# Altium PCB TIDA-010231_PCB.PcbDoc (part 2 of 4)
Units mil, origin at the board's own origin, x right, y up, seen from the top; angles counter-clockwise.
Board outline 3937.01 x 3740.16 mil, 4 copper layers (Top Layer, Signal Layer 1, Signal Layer 2, Bottom Layer), stack 65.355 mil thick; 295 components, 163 nets, 818 pads, 213 vias.
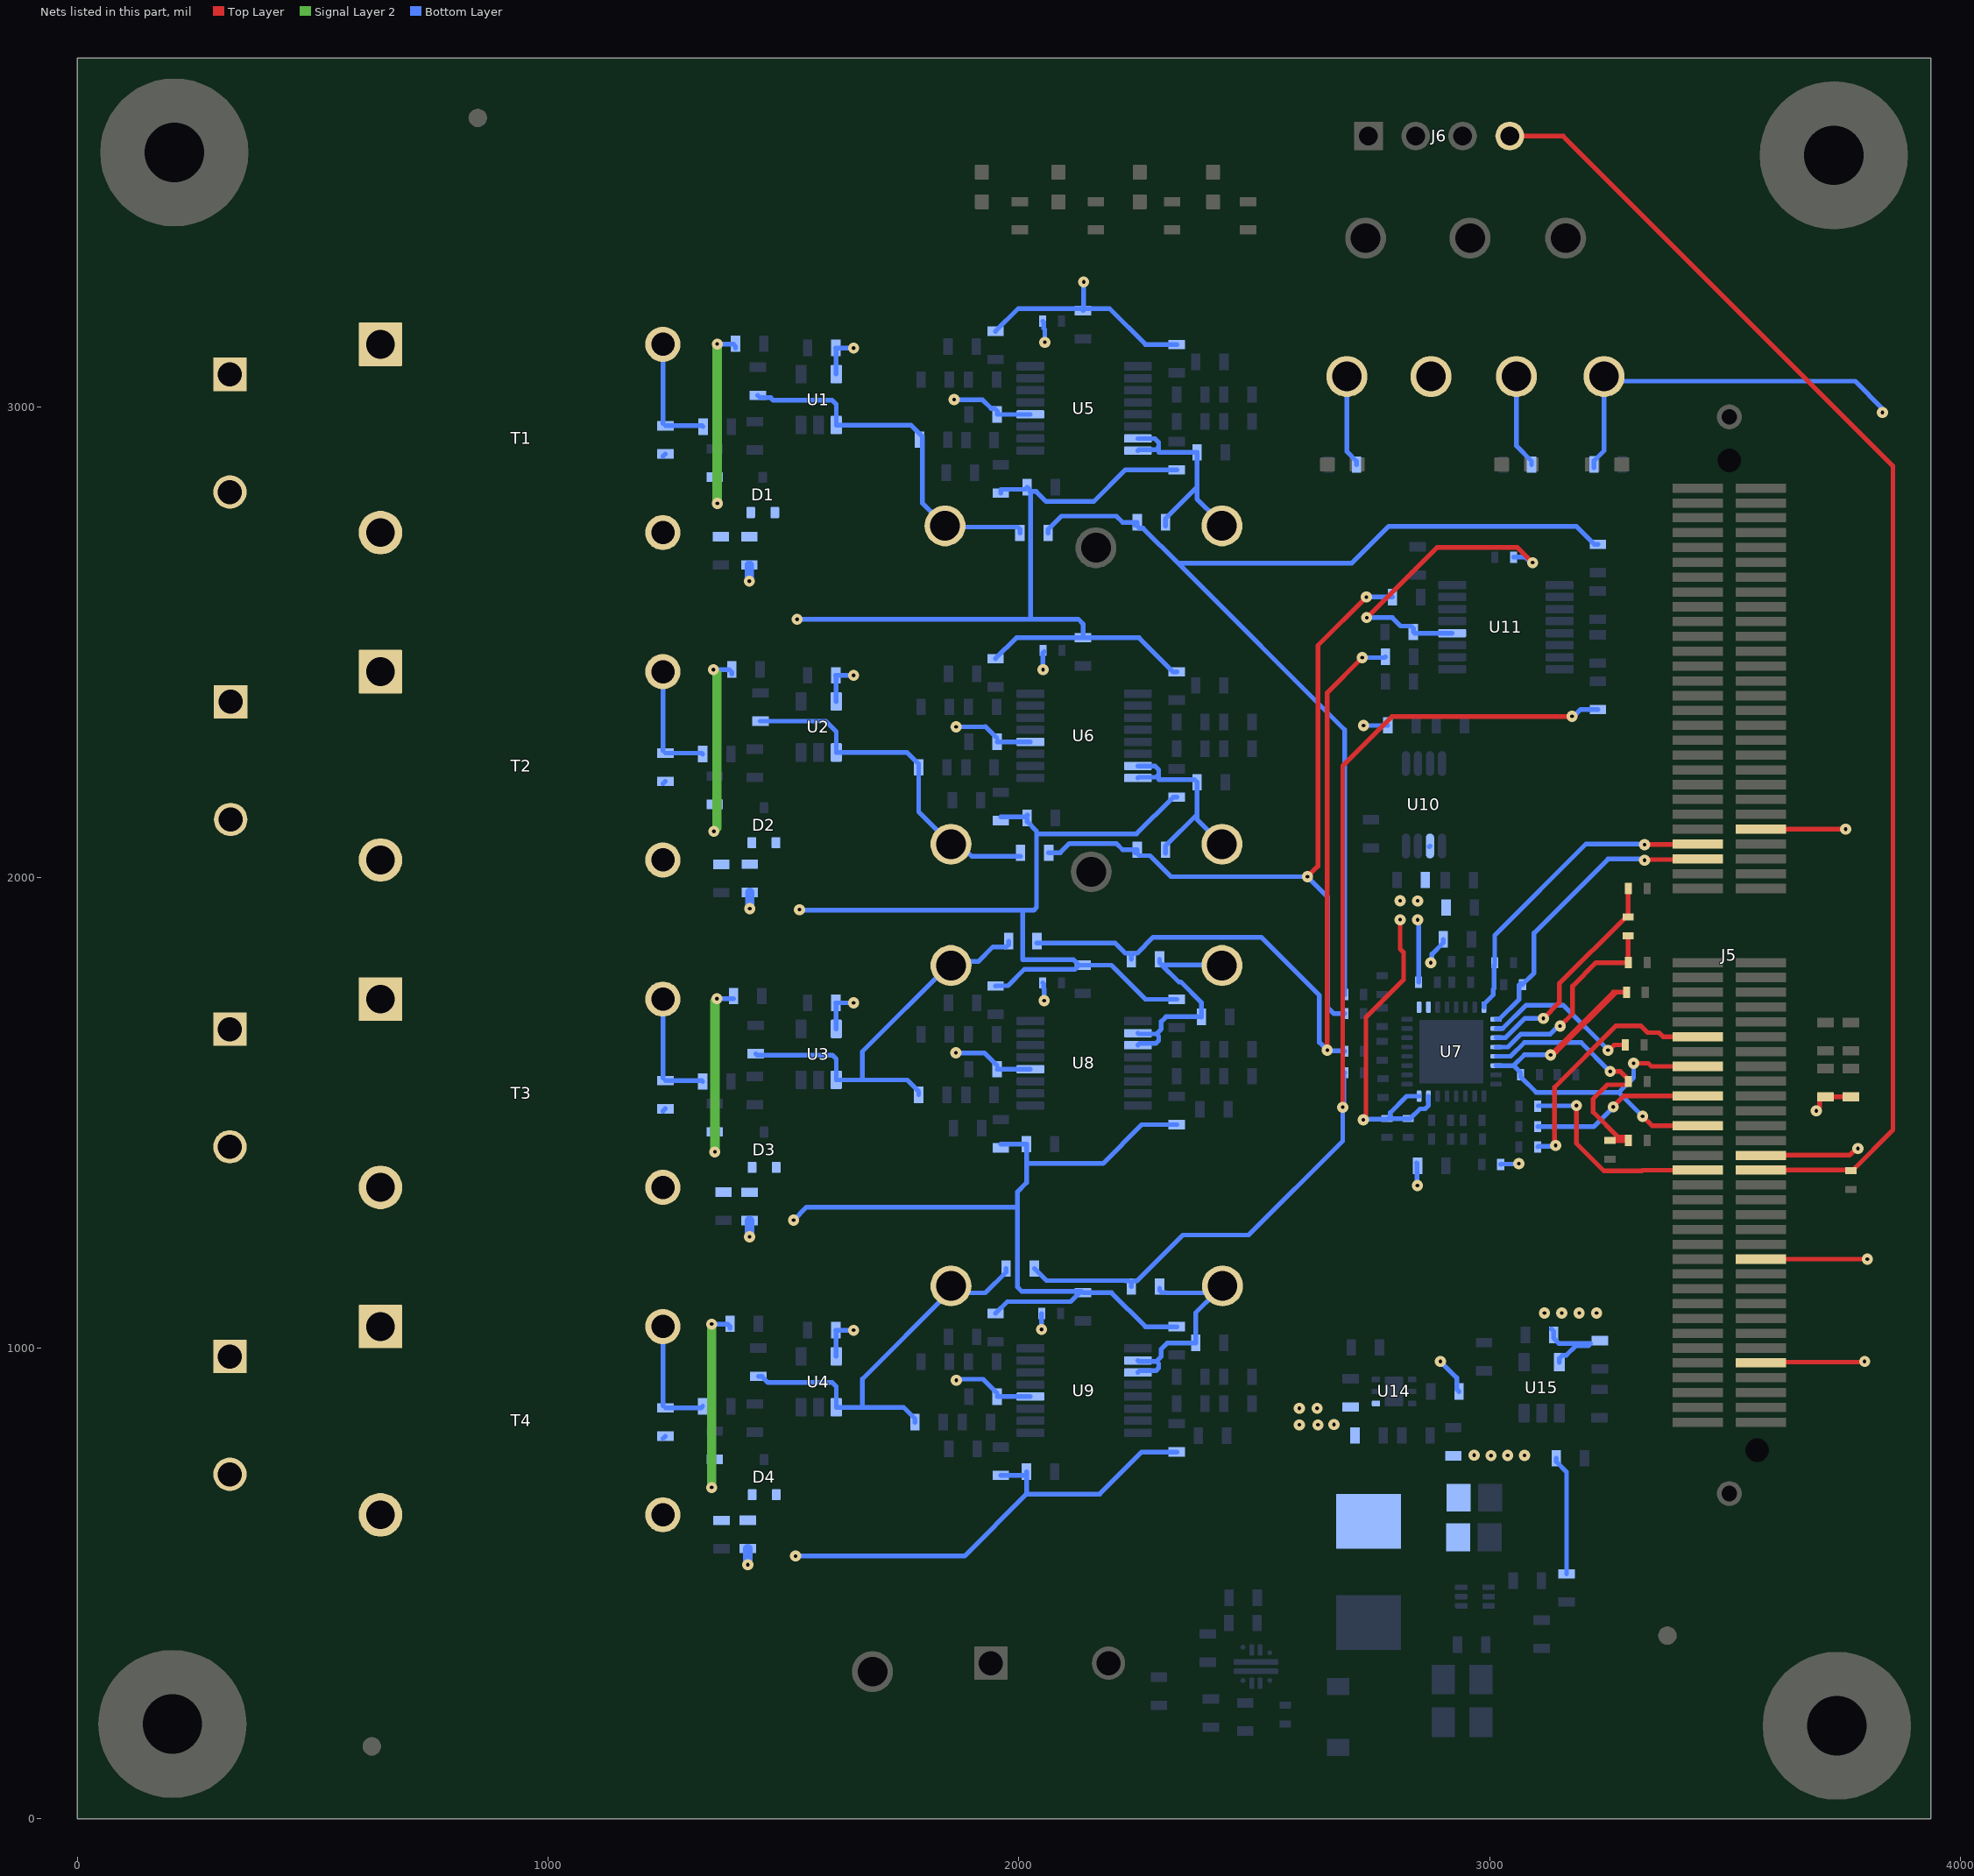
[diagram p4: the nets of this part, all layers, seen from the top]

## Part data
C1 C3 C5 C7: library part CMP-0006898-4, "CAP, CERM, 2200 pF, 50 V, +/- 10%, X7R, 0603", Cap_Case=0603, Manufacturer=Kemet, Supplier Part Number 1=399-1085-1-ND, TempCo=X7R, Tolerance_%=10%, Value1=Unknown, Value2=50V, ValueDisplayed=2200pF
C2 C4 C6 C8 C9 C10 C19 C20 C38 C39 C50 C51 C67 C68 C69 C70 C71 C87 C88 C89 C90: library part CMP-0079602-1, "CAP, CERM, 0.1 µF, 50 V,+/- 10%, X7R, AEC-Q200 Grade 1, 0603", Cap_Case=0603, Manufacturer=Kemet, Supplier Part Number 1=399-6856-1-ND, TempCo=X7R, Tolerance_%=10%, Value2=50V, ValueDisplayed=0.1µF
C11 C12 C25 C26 C40 C41 C54 C55: library part CMP-0006751-4, "CAP, CERM, 100 pF, 25 V, +/- 10%, X7R, 0603", Cap_Case=0603, Manufacturer=AVX, Supplier Part Number 1=55J3899, TempCo=X7R, Tolerance_%=10%, Value1=Unknown, Value2=25V, ValueDisplayed=100pF
C13 C27 C42 C56: library part CMP-0007162-4, "CAP, CERM, 1300 pF, 25 V, +/- 5%, C0G/NP0, 0603", Cap_Case=0603, Manufacturer=MuRata, Supplier Part Number 1=GRM1885C1E132JA01D-ND, TempCo=C0G/NP0, Tolerance_%=5%, Value1=Unknown, Value2=25V, ValueDisplayed=1300pF
C14 C28 C43 C57: library part CMP-0007432-5, "CAP, CERM, 1000 pF, 50 V, +/- 10%, X7R, 0603", Cap_Case=0603, Manufacturer=MuRata, Supplier Part Number 1=490-1494-1-ND, TempCo=X7R, Tolerance_%=10%, Value1=Unknown, Value2=50V, ValueDisplayed=1000pF
C15 C29 C44 C58: library part CMP-0007216-4, "CAP, CERM, 3900 pF, 50 V, +/- 5%, C0G/NP0, 0603", Cap_Case=0603, Manufacturer=MuRata, Supplier Part Number 1=GRM1885C1H392JA01D-ND, TempCo=C0G/NP0, Tolerance_%=5%, Value1=Unknown, Value2=50V, ValueDisplayed=3900pF
C16 C30 C45 C59: library part CMP-0006983-4, "CAP, CERM, 2200 pF, 50 V, +/- 10%, X7R, 0603", Cap_Case=0603, Manufacturer=Kemet, Supplier Part Number 1=399-5341-1-ND, TempCo=X7R, Tolerance_%=10%, Value1=Unknown, Value2=50V, ValueDisplayed=2200pF
C17 C33 C47 C61: library part CMP-0007185-4, "CAP, CERM, 150 pF, 50 V, +/- 5%, C0G/NP0, 0603", Cap_Case=0603, Manufacturer=MuRata, Supplier Part Number 1=490-1431-1-ND, TempCo=C0G/NP0, Tolerance_%=5%, Value1=Unknown, Value2=50V, ValueDisplayed=150pF
C18 C34 C48 C62: library part CMP-0006784-4, "CAP, CERM, 330 pF, 50 V, +/- 5%, C0G/NP0, 0603", Cap_Case=0603, Manufacturer=AVX, Supplier Part Number 1=478-1181-1-ND, TempCo=C0G/NP0, Tolerance_%=5%, Value1="0.071 ohm", Value2=50V, ValueDisplayed=330pF
C21 C24 C31: library part CMP-0006638-2, "CAP, CERM, 1000 pF, 16 V, +/- 10%, X7R, 0402", Cap_Case=0402, Manufacturer=MuRata, Supplier Part Number 1=GRM155R71C102KA01D-ND, TempCo=X7R, Tolerance_%=10%, Value1=Unknown, Value2=16V, ValueDisplayed=1000pF
C22 C23 C32: library part CMP-0006624-2, "CAP, CERM, 1 uF, 6.3 V, +/- 20%, X7R, 0402", Cap_Case=0402, Manufacturer=MuRata, Supplier Part Number 1=490-9665-1-ND, TempCo=X7R, Tolerance_%=20%, Value1=Unknown, Value2=6.3V, ValueDisplayed=1uF
C35: library part CMP-0006233-2, "CAP, CERM, 100 pF, 25 V, +/- 5%, C0G/NP0, 0402", Cap_Case=0402, Manufacturer=Kemet, Supplier Part Number 1=399-1022-1-ND, TempCo=C0G/NP0, Tolerance_%=5%, Value1=Unknown, Value2=25V, ValueDisplayed=100pF
C36 C37 C49 C52: library part CMP-0079620-1, "CAP, CERM, 1500 pF, 50 V,+/- 5%, X7R, 0402", Cap_Case=0402, Manufacturer=MuRata, Supplier Part Number 1=490-10779-1-ND, TempCo=X7R, Tolerance_%=5%, Value2=50V, ValueDisplayed=1500pF
C46 C60: library part CMP-0006564-2, "CAP, CERM, 10 uF, 10 V, +/- 20%, X5R, 0402", Cap_Case=0402, Manufacturer=MuRata, TempCo=X5R, Tolerance_%=20%, Value1=Unknown, Value2=10V, ValueDisplayed=10uF
C53: library part CMP-0006545-2, "CAP, CERM, 22 uF, 6.3 V, +/- 20%, X5R, 0402", Cap_Case=0402, Manufacturer=MuRata, TempCo=X5R, Tolerance_%=20%, Value1=Unknown, Value2=6.3V, ValueDisplayed=22uF
C63: library part CMP-0007497-5, "CAP, CERM, 10 uF, 10 V, +/- 20%, X7R, 0603", Cap_Case=0603, Manufacturer=MuRata, Supplier Part Number 1=81-GRM188Z71A106MA3D, TempCo=X7R, Tolerance_%=20%, Value1=Unknown, Value2=10V, ValueDisplayed=10uF
C64 C65 C85 C86: library part CMP-0076705-3, "CAP, CERM, 1 µF, 25 V,+/- 10%, X7R, AEC-Q200 Grade 1, 0603", Cap_Case=1.6x0.8x0.8mm, Manufacturer=TDK, Supplier Part Number 1=445-6931-1-ND, TempCo=X7R, Tolerance_%=10%, Value2=25V, ValueDisplayed=1µF
C66 C79: library part CMP-0007313-5, "CAP, CERM, 47 uF, 6.3 V, +/- 20%, X5R, 0603", Cap_Case=0603, Manufacturer=MuRata, TempCo=X5R, Tolerance_%=20%, Value1=Unknown, Value2=6.3V, ValueDisplayed=47uF
C72: library part CMP-0007011-5, "CAP, CERM, 1 uF, 50 V, +/- 10%, X5R, 0603", Cap_Case=0603, Manufacturer=TDK, Supplier Part Number 1=445-7468-1-ND, TempCo=X5R, Tolerance_%=10%, Value1="0.005522 ohm", Value2=50V, ValueDisplayed=1uF
C73 C76 C83: library part CMP-0006856-6, "CAP, CERM, 0.1 uF, 25 V, +/- 5%, X7R, 0603", Cap_Case=0603, Manufacturer=Kemet, Supplier Part Number 1=399-1282-1-ND, TempCo=X7R, Tolerance_%=5%, Value1=Unknown, Value2=25V, ValueDisplayed=0.1uF
C74 C75: library part CMP-0008207-2, "CAP, CERM, 10 uF, 25 V, +/- 20%, X5R, 0805", Cap_Case=0805, Manufacturer=MuRata, TempCo=X5R, Tolerance_%=20%, Value1=Unknown, Value2=25V, ValueDisplayed=10uF
C77: library part CMP-0007498-4, "CAP, CERM, 4.7 uF, 10 V, +/- 20%, X7R, 0603", Cap_Case=0603, Manufacturer=MuRata, TempCo=X7R, Tolerance_%=20%, Value1=Unknown, Value2=10V, ValueDisplayed=4.7uF
C80 C81: library part CMP-0008286-2, "CAP, CERM, 22 uF, 10 V, +/- 20%, X5R, 0805", Cap_Case=0805, Manufacturer=MuRata, Supplier Part Number 1=490-10746-1-ND, TempCo=X5R, Tolerance_%=20%, Value1=Unknown, Value2=10V, ValueDisplayed=22uF
C84: library part CMP-0006411-2, "CAP, CERM, 1000 pF, 50 V, +/- 1%, C0G/NP0, 0402", Cap_Case=0402, Manufacturer=MuRata, Supplier Part Number 1=490-6189-1-ND, TempCo=C0G/NP0, Tolerance_%=1%, Value1=Unknown, Value2=50V, ValueDisplayed=1000pF
D1 D2 D3 D4: library part CMP-0077035-2, "Diode, Switching, 75 V, 0.15 A, SOT-323", Manufacturer="Diodes Inc.", Value1=0.15A, Value2=1.25V
D5 D6 D7 D8 D10 D11 D12: library part CMP-0081648-2, "LED, Green, SMD", Color=Green, Manufacturer="Wurth Elektronik", Power_TotalModule=48mW, Value1=0.048W, Value2=2V
D9: library part CMP-0085140-1, "Diode, Zener, 17 V, 500 mW, SOD-123", Manufacturer="Diodes Inc.", Power_W=500mW, Value1=0.5W
FID1 FID2 FID3 FID4 FID5 FID6: library part CMP-0077181-1, "Fiducial mark.  There is nothing to buy or mount.", Manufacturer=N/A
H1 H2 H3 H4: library part CMP-0003617-1, "Machine Screw, Round, #4-40 x 1/4, Nylon, Philips panhead", Manufacturer="B&F Fastener Supply", Supplier Part Number 1=H542-ND
H5 H6 H7 H8: library part CMP-0003610-1, "Standoff, Hex, 0.5\"L #4-40 Nylon", Manufacturer=Keystone, Supplier Part Number 1=36-1902C-ND
J1 J2 J3 J4 J7: library part CMP-0055505-1, "Terminal Block, 2x1, 6.35mm, Green, TH", Color=Green, Manufacturer="Phoenix Contact", Supplier Part Number 1=277-1269-ND
J5: library part CMP-0003814-2, "C2000 controlCARD-120HSEC connector, SMT", Manufacturer=Samtec
J6: library part CMP-0055331-1, "Header, 2.54mm, 4x1, Tin, TH", Color=Black, Current_A=4A, Manufacturer=Molex, Supplier Part Number 1=WM50016-04-ND, Voltage_V=250V
L1 L2: library part CMP-0003195-2, "Ferrite Bead, 470 ohm @ 100 MHz, 1 A, 0603", Manufacturer="Wurth Elektronik", Supplier Part Number 1=732-4667-1-ND, Value1="0.2 ohm", Value2=1A, ValueDisplayed="470 ohm"
L3: library part CMP-0064108-1, "Inductor, Shielded Drum Core, Powdered Iron, 4.7 uH, 5 A, 0.028 ohm, SMD", Manufacturer="Wurth Elektronik", Supplier Part Number 1=732-3354-1-ND, Value1="0.028 ohm", Value2=5A, ValueDisplayed=4.7uH
LBL1: library part CMP-0003625-1, "Thermal Transfer Printable Labels, 0.650\" W x 0.200\" H - 10,000 per roll", Manufacturer=Brady, Supplier Part Number 1=97C5133
Logo1: library part CMP-0074838-1, "Texas Instrument Corporate Signature"
Logo2: library part CMP-0074847-1, "FCC_disclaimer"
Logo3: library part CMP-0074769-1
"LOGO HV": library part CMP-0074835-1, "IEC 61010-1 High Voltage Warning"
LogoCE: library part CMP-0074844-1
LOGOHotSurface: library part CMP-0074837-2, "IEC 61010-1 Hot Surface Warning", Manufacturer="Texas Instruments"
R1 R6 R11 R16: library part CMP-0022109-5, "RES, 1.00 k, 1%, 0.1 W, AEC-Q200 Grade 0, 0603", Manufacturer=Vishay-Dale, Power_W=100mW, Supplier Part Number 1=541-1.00KHCT-ND, TempCo="100 ppm/C", Tolerance_%=1%, Value2=0.1W, Value_Code=1k00, ValueDisplayed=1.00k
R2 R7 R12 R17: library part CMP-0022665-4, "RES, 9.09 k, 1%, 0.1 W, AEC-Q200 Grade 0, 0603", Manufacturer=Vishay-Dale, Power_W=100mW, Supplier Part Number 1=541-9.09KHCT-ND, TempCo="100 ppm/C", Tolerance_%=1%, Value2=0.1W, Value_Code=9k09, ValueDisplayed=9.09k
R3 R8 R13 R18: library part CMP-0022448-4, "RES, 49.9, 1%, 0.1 W, AEC-Q200 Grade 0, 0603", Manufacturer=Vishay-Dale, Power_W=100mW, Supplier Part Number 1=541-49.9HCT-ND, TempCo="100 ppm/C", Tolerance_%=1%, Value2=0.1W, Value_Code=49R9, ValueDisplayed=49.9
R4 R9 R14 R19: library part CMP-0021991-4, "RES, 100, 1%, 0.1 W, AEC-Q200 Grade 0, 0603", Manufacturer=Vishay-Dale, Power_W=100mW, Supplier Part Number 1=541-100HCT-ND, TempCo="100 ppm/C", Tolerance_%=1%, Value2=0.1W, Value_Code=100R, ValueDisplayed=100
R5 R10 R15 R20: library part CMP-0023462-3, "RES, 200, 0.1%, 0.1 W, 0603", Manufacturer="Susumu Co Ltd", Power_W=100mW, Supplier Part Number 1=RG16P200BCT-ND, TempCo="25 ppm/C", Tolerance_%=0.1%, Value2=0.1W, Value_Code=200R, ValueDisplayed=200
R21 R22 R23 R32 R33 R34 R49 R50 R53 R63 R64 R65: library part CMP-0025932-5, "RES, 5.1 k, 5%, 0.1 W, 0603", Manufacturer=Yageo, Power_W=100mW, Supplier Part Number 1=311-5.1KGRCT-ND, TempCo="100 ppm/C", Tolerance_%=5%, Value2=0.1W, Value_Code=5k10, ValueDisplayed=5.1k
R24 R35 R54 R66: library part CMP-0078661-1, "RES, 16.0 k, 1%, 0.1 W, AEC-Q200 Grade 0, 0603", Manufacturer=Panasonic, Power_W=100mW, Supplier Part Number 1=P16.0KHCT-ND, TempCo="100 ppm/C", Tolerance_%=1%, Value2=0.1W, Value_Code=16k0, ValueDisplayed=16.0k
R25 R36 R55 R67: library part CMP-0082531-1, "RES, 3.30 k, 1%, 0.1 W, AEC-Q200 Grade 0, 0603", Manufacturer=Vishay-Dale, Power_W=100mW, Supplier Part Number 1=541-3.30KHCT-ND, TempCo="100 ppm/C", Tolerance_%=1%, Value2=0.1W, Value_Code=3k30, ValueDisplayed=3.30k
R26 R37 R56 R68: library part CMP-0023333-5, "RES, 9.10 k, 1%, 0.1 W, 0603", Manufacturer=Yageo, Power_W=100mW, Supplier Part Number 1=311-9.10KHRCT-ND, TempCo="100 ppm/C", Tolerance_%=1%, Value2=0.1W, Value_Code=9k10, ValueDisplayed=9.10k
R27 R30 R38 R44 R57 R61 R69 R72 R73 R100 R101 R102 R103 R106 R116 R120 R121 R122 R123: library part CMP-0023343-3, "RES, 0, 1%, 0.1 W, AEC-Q200 Grade 0, 0603", Manufacturer="Stackpole Electronics Inc", Power_W=100mW, Supplier Part Number 1=RMCF0603ZT0R00CT-ND, TempCo=ppm/C, Tolerance_%=1%, Value2=0.1W, Value_Code=0
R28 R40 R58 R70: library part CMP-0025816-4, "RES, 4.3 k, 5%, 0.1 W, AEC-Q200 Grade 0, 0603", Manufacturer=Vishay-Dale, Power_W=100mW, Supplier Part Number 1=541-4.3KGCT-ND, TempCo="200 ppm/C", Tolerance_%=5%, Value2=0.1W, Value_Code=4k30, ValueDisplayed=4.3k
R29 R41 R59 R71: library part CMP-0025841-4, "RES, 680, 5%, 0.1 W, AEC-Q200 Grade 0, 0603", Manufacturer=Vishay-Dale, Power_W=100mW, Supplier Part Number 1=541-680GCT-ND, TempCo="200 ppm/C", Tolerance_%=5%, Value2=0.1W, Value_Code=680R, ValueDisplayed=680
R31 R42 R86: library part CMP-0026822-3, "RES, 0, 5%, 0.063 W, AEC-Q200 Grade 0, 0402", Manufacturer=Vishay-Dale, Power_W=63mW, Supplier Part Number 1=541-0.0JCT-ND, TempCo="200 ppm/C", Tolerance_%=5%, Value2=0.063W, Value_Code=0000, ValueDisplayed=0
R39 R45 R60 R62: library part CMP-0026955-3, "RES, 5.1, 5%, 0.063 W, AEC-Q200 Grade 0, 0402", Manufacturer=Vishay-Dale, Power_W=63mW, Supplier Part Number 1=541-5.1JCT-ND, TempCo="200 ppm/C", Tolerance_%=5%, Value2=0.063W, Value_Code=5R10, ValueDisplayed=5.1
R43: library part CMP-0026974-3, "RES, 75, 5%, 0.063 W, AEC-Q200 Grade 0, 0402", Manufacturer=Vishay-Dale, Power_W=63mW, Supplier Part Number 1=541-75JCT-ND, TempCo="200 ppm/C", Tolerance_%=5%, Value2=0.063W, Value_Code=75R0, ValueDisplayed=75
R46 R47 R48: library part CMP-0082623-1, "RES, 50, 2%, 0.05 W, 0402", Manufacturer="Vishay Sfernice", Power_W=50mW, Supplier Part Number 1=71-CH0402-50RGFPT, TempCo="100 ppm/C", Tolerance_%=2%, Value2=0.05W, Value_Code=50R0, ValueDisplayed=50
R51 R52 R75 R76 R77 R78 R98 R99: library part CMP-0026825-5, "RES, 10 k, 5%, 0.063 W, AEC-Q200 Grade 0, 0402", Manufacturer=Vishay-Dale, Power_W=63mW, Supplier Part Number 1=541-10KJCT-ND, TempCo="200 ppm/C", Tolerance_%=5%, Value2=0.063W, Value_Code=10k0, ValueDisplayed=10k
R74: library part CMP-0025743-4, "RES, 1.0, 5%, 0.1 W, AEC-Q200 Grade 0, 0603", Manufacturer=Vishay-Dale, Power_W=100mW, Supplier Part Number 1=541-1.0GCT-ND, TempCo="200 ppm/C", Tolerance_%=5%, Value2=0.1W, Value_Code=1R00, ValueDisplayed=1.0
R79 R80 R83 R84: library part CMP-0022438-4, "RES, 47.0 k, 1%, 0.1 W, AEC-Q200 Grade 0, 0603", Manufacturer=Vishay-Dale, Power_W=100mW, Supplier Part Number 1=541-47.0KHCT-ND, TempCo="100 ppm/C", Tolerance_%=1%, Value2=0.1W, Value_Code=47k0, ValueDisplayed=47.0k
R81 R82 R90 R91: library part CMP-0023318-5, "RES, 91.0 k, 1%, 0.1 W, 0603", Manufacturer=Yageo, Power_W=100mW, Supplier Part Number 1=311-91.0KHRCT-ND, TempCo="100 ppm/C", Tolerance_%=1%, Value2=0.1W, Value_Code=91k0, ValueDisplayed=91.0k
R85 R87 R92 R95 R96 R97: library part CMP-0026936-3, "RES, 47, 5%, 0.063 W, AEC-Q200 Grade 0, 0402", Manufacturer=Vishay-Dale, Power_W=63mW, Supplier Part Number 1=541-47JCT-ND, TempCo="200 ppm/C", Tolerance_%=5%, Value2=0.063W, Value_Code=47R0, ValueDisplayed=47
R88 R89 R93 R94 R108 R111 R117: library part CMP-0025859-4, "RES, 820, 5%, 0.1 W, AEC-Q200 Grade 0, 0603", Manufacturer=Vishay-Dale, Power_W=100mW, Supplier Part Number 1=541-820GCT-ND, TempCo="200 ppm/C", Tolerance_%=5%, Value2=0.1W, Value_Code=820R, ValueDisplayed=820
R104: library part CMP-0023128-4, "RES, 470 k, 1%, 0.1 W, 0603", Manufacturer=Yageo, Power_W=100mW, Supplier Part Number 1=311-470KHRCT-ND, TempCo="100 ppm/C", Tolerance_%=1%, Value2=0.1W, Value_Code=470k
R105: library part CMP-0023267-5, "RES, 75.0 k, 1%, 0.1 W, 0603", Manufacturer=Yageo, Power_W=100mW, Supplier Part Number 1=311-75.0KHRCT-ND, TempCo="100 ppm/C", Tolerance_%=1%, Value2=0.1W, Value_Code=75k0, ValueDisplayed=75.0k
R107: library part CMP-0022499-4, "RES, 56.2 k, 1%, 0.1 W, AEC-Q200 Grade 0, 0603", Manufacturer=Vishay-Dale, Power_W=100mW, Supplier Part Number 1=541-56.2KHCT-ND, TempCo="100 ppm/C", Tolerance_%=1%, Value2=0.1W, Value_Code=56k2, ValueDisplayed=56.2k
R109: library part CMP-0025824-4, "RES, 51 k, 5%, 0.1 W, AEC-Q200 Grade 0, 0603", Manufacturer=Vishay-Dale, Power_W=100mW, Supplier Part Number 1=541-51KGCT-ND, TempCo="200 ppm/C", Tolerance_%=5%, Value2=0.1W, Value_Code=51k0, ValueDisplayed=51k
R110: library part CMP-0023812-3, "RES, 174 k, 0.1%, 0.1 W, 0603", Manufacturer="Yageo America", Power_W=100mW, TempCo="25 ppm/C", Tolerance_%=0.1%, Value2=0.1W, Value_Code=174k
R112: library part CMP-0023112-5, "RES, 43.2 k, 1%, 0.1 W, 0603", Manufacturer=Yageo, Power_W=100mW, Supplier Part Number 1=311-43.2KHRCT-ND, TempCo="100 ppm/C", Tolerance_%=1%, Value2=0.1W, Value_Code=43k2, ValueDisplayed=43.2k
R113: library part CMP-0023202-5, "RES, 5.62 k, 1%, 0.1 W, 0603", Manufacturer=Yageo, Power_W=100mW, Supplier Part Number 1=311-5.62KHRCT-ND, TempCo="100 ppm/C", Tolerance_%=1%, Value2=0.1W, Value_Code=5k62, ValueDisplayed=5.62k
R114 R118 R119: library part CMP-0021998-4, "RES, 10.0 k, 1%, 0.1 W, AEC-Q200 Grade 0, 0603", Manufacturer=Vishay-Dale, Power_W=100mW, Supplier Part Number 1=541-10.0KHCT-ND, TempCo="100 ppm/C", Tolerance_%=1%, Value2=0.1W, Value_Code=10k0, ValueDisplayed=10.0k
R115: library part CMP-0023945-3, "RES, 21.5 k, 0.1%, 0.1 W, 0603", Manufacturer="Yageo America", Power_W=100mW, TempCo="25 ppm/C", Tolerance_%=0.1%, Value2=0.1W, Value_Code=21k5, ValueDisplayed=21.5k
T1 T2 T3 T4: library part CMP-0092760-1, "38 A - Current Sense Transformer 10kHz ~ 200kHz 200Ohm Primary, 4.5Ohm Secondary 80 mH Through Hole", Digikey Part Number=553-1554-ND, Frequency_Fixed=10-200kHz, Manufacturer="Pulse Electronics Corporation", Mouser Part Number=673-PE-67200NL, Operating Temperature Range="-40°C to +130°C", Voltage_Isolation_Vrms=4.25kV
TP1 TP2 TP3 TP4 TP5 TP6 TP7 TP8 TP9 TP10 TP11 TP12 TP13 TP14 TP15 TP16 TP17 TP18: library part CMP-0055144-2, "Test Point, Compact, White, TH", Color=White, Manufacturer="Keystone Electronics", Supplier Part Number 1=36-5007-ND
U1 U2 U3 U4: library part CMP-0040891-1, "20 MHz, Low Noise, RRIO, CMOS Operational Amplifier with Shutdown, 1.8 to 5.5 V, -40 to 125 degC, 5-pin SOT23 (DBV5), Green (RoHS & no Sb/Br)", Manufacturer="Texas Instruments", Rating=Catalog, Total Supply Voltage(Max)(+5V is 5, +/-5V is 10)=5.5, Total Supply Voltage(Min)(+5V is 5, +/-5V is 10)=1.8
U5 U6 U8 U9 U11: library part CMP-0093017-1, "CMOS Amplifier 4 Circuit Rail-to-Rail 16-TSSOP", Digikey Part Number=296-30575-1-ND, Input Bias Current=0.0000002uA, Input Offset Voltage=0.5mV, Manufacturer="Texas Instruments", Max Dual Supply Voltage=2.75V, Max Supply Voltage=5.5V, Min Dual Supply Voltage=900mV, Min Supply Voltage=1.8V, Mouser Part Number=595-OPA4322SAIPWR, Nominal Supply Current=1.4mA, Operating Temperature Range="-40°C to +125°C", Output Current Per Channel=65mA, Voltage Gain=130dB
U7: library part CMP-0075960-1, "16-Bit, 1-MSPS, 4x2/2x2 Simultaneous-Sampling SAR ADC, RHB0032E (VQFN-32)", Alternate Manufacturer="Texas Instruments", Alternate PartNumber=ADS8363SRHBT
U10: library part CMP-0032584-2, "3 µVpp/V Noise, 3 ppm/°C Drift Precision Series Voltage Reference, DGK0008A (VSSOP-8)", Manufacturer="Texas Instruments", Rating=Military, Temp Coeff(Max)(ppm/ degree C)=3
U12: library part CMP-0092031-1, "2.7-V to 23-V, 28-mΩ, 5.5-A eFuse with integrated reverse polarity protection 10-VQFN-HR -40 to 125", Manufacturer="Texas Instruments", Max Supply Voltage=23V, Min Supply Voltage=2.7V, Nominal Supply Current=74-429uA, Operating Temperature Range="-40°C to +125°C", Output Voltage=23-43V, Threshold Voltage=1.2/1.1V
U13: library part CMP-0860978-1, "TPS562202DRLR, DRL0006A (SOT-5X3-6)", Alternate Manufacturer="Texas Instruments"
U14: library part CMP-0082614-1, "500-mA LDO With Power-Good, DRV0006A (WSON-6)", Alternate Manufacturer="Texas Instruments", Alternate PartNumber=TPS74501PDRVT, Operating Temperature Range="-40 to 125 C"
U15: library part CMP-0860155-1, "Automotive capacitor-free 300-mA LDO regulator with foldback current limit for portable devices, DBV0005A (SOT-23-5)", Alternate Manufacturer="Texas Instruments", Operating Temperature Range="-40 to 125,-40 to 150 C", Rating=Automotive
ZZ1: library part CMP-0003616-3
ZZ2: library part CMP-0077236-1
ZZ3: library part CMP-0077237-1
ZZ4: library part CMP-0077238-1

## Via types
v1: diameter 23.62, hole 7.87, Top Layer to Bottom Layer, 211 vias
v2: diameter 19.68, hole 7.87, Top Layer to Bottom Layer, 2 vias

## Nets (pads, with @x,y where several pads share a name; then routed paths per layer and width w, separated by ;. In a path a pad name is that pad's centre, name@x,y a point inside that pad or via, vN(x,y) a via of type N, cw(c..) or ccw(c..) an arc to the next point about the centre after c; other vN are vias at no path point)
2V5: C9.1 C10.1 C11.1 C12.1 C19.1 C20.1 C25.1 C26.1 C38.1 C39.1 C40.1 C41.1 C46.1 C50.1 C51.1 C53.2 C54.1 C55.1 C60.1 C64.1 R21.2 R22.2 R32.2 R33.2 R49.2 R50.2 R63.2 R64.2 R74.2 R120.1 R121.1 R122.1 R123.1 TP9.1 U7.9 U7.10 U7.31 U7.32 U10.6 | length 7797.2
  Top Layer w10: v1@2737.17,1494.14 2737.17,1702.43 2817.37,1782.62 2817.37,1840.77 2809.86,1848.29 v1(2809.86,1910.12)
  Bottom Layer w10: v1@1520.44,1270.92 1548.99,1299.47 1997.02,1299.47 ; v1(1525.45,558.2) 1884.34,558.2 2016.14,690.01 ; v1(1528.65,2548.29) 2023.35,2548.29 ; v1(1533.78,1931.53) 1535.03,1930.28 2008.21,1930.28 ; C55.1@1950.28,1073.6 1975.48,1098.8 2109.91,1098.8 C51.1@2128.74,1117.63 ; C41.1@1950.28,1769.11 1951.06,1769.89 1976.92,1769.89 2011.7,1804.66 2119.24,1804.66 C39.1@2128.05,1813.47 ; C26.1@1950.28,2464.62 1994.82,2509.16 C20.1@2136.3,2509.16 ; C12.1@1950.28,3160.13 1998.38,3208.23 2192.68,3208.23 2268.84,3132.07 R21.2@2335.47,3132.07 ; C54.1@1961.35,729.79 C50.1@2011.14,729.79 ; C40.1@1961.35,1433.18 C38.1@2016.14,1433.18 2016.14,1392.3 ; C25.1@1961.35,2128.69 C19.1@2014.31,2128.69 ; C11.1@1961.35,2816.33 1961.35,2824.2 2012.95,2824.2 C9.1@2017.47,2828.72 2025.07,2821.12 2025.07,2550.02 2023.35,2548.29 ; C50.1@2016.14,737.66 2016.14,703.95 2016.14,690.01 ; C19.1@2018.1,2132.47 C19.1@2014.31,2128.69 ; C9.1@2022.47,2819.89 2036.62,2819.89 2058.16,2798.35 2158.8,2798.35 2226.32,2865.87 R22.2@2335.47,2865.87 ; C10.1@2136.3,3203.91 2137.67,3205.28 v1(2137.67,3265.07) ; R63.2@2335.47,779.33 2261,779.33 2171.68,690.01 2016.14,690.01 ; R64.2@2335.47,1045.53 2268.84,1045.53 2196.74,1117.63 C51.1@2136.24,1117.63 2133.26,1120.61 2005.88,1120.61 1997.02,1129.47 1997.02,1299.47 ; R49.2@2335.47,1474.84 2261,1474.84 2178.46,1392.3 2016.14,1392.3 ; R50.2@2335.47,1741.04 2268.84,1741.04 2196.41,1813.47 C39.1@2135.55,1813.47 C39.1@2128.05,1813.47 ; R33.2@2335.47,2170.35 2327.97,2170.35 2249.99,2092.37 2037.29,2092.37 ; R32.2@2335.47,2436.56 2327.97,2436.56 2255.37,2509.16 C20.1@2136.3,2509.16 ; v1(2731.77,1484.95) 2733.06,1486.24 2781.3,1486.24 C60.1@2782.14,1487.08 ; C60.1@2782.14,1487.52 C60.1@2786.64,1487.52 ; v1(2847.01,1909.84) 2849.33,1907.53 C53.2@2849.33,1777.75 ; U7.32@2850.28,1535.23 2823.99,1535.23 2789.14,1500.38 2789.14,1490.02 C60.1@2786.64,1487.52 ; U7.31@2869.96,1535.23 2869.89,1535.15 2869.89,1514.96 2863.19,1508.26 2852.25,1508.26 2831.52,1487.52 C46.1@2827.02,1487.52 C60.1@2786.64,1487.52 ; U10.6@2871.87,2065.22 U10.6@2873.35,2066.7 ; 1997.02,1299.47 1997.02,1332.31 2016.14,1351.43 2016.14,1392.3 ; 2008.21,1930.28 2031.43,1930.28 2037.29,1936.13 2037.29,2092.37 ; 2008.21,1930.28 2008.21,1824.97 2116.56,1824.97 C39.1@2128.05,1813.47 ; C19.1@2014.31,2128.69 2014.81,2128.69 C19.1@2017.47,2126.02 2017.47,2118.52 2037.29,2098.71 2037.29,2092.37 ; 2023.35,2548.29 2126.52,2548.29 2136.3,2538.52 C20.1@2136.3,2509.16
  Bottom Layer w20: v1(1424.01,539.66) R123.1@1424.01,574.14 ; v1(1427.41,2629.16) R120.1@1427.41,2663.64 ; v1(1427.82,1236.44) R122.1@1427.82,1270.92 ; v1(1428.2,1933.54) R121.1@1428.2,1968.02
  other v1: 1521.5,1271.81 2809.86,1950.35 2847.01,1950.13
3V3: C71.1 C86.1 R31.2 R98.2 R100.2 R101.1 R117.2 R118.2 TP18.1 U11.4 U15.5 | length 1203.7
  Top Layer w10: v1(2738.95,2551.83) 2887.99,2700.87 3059.11,2700.87 v1(3091.31,2668.67) ; v1(3694.1,1504.02) 3701.28,1511.21 3701.28,1528.91 3706.28,1533.91 R101.1@3713.78,1533.91 R100.2@3767.67,1533.91
  Bottom Layer w10: v1@2737.17,2550.06 v1(2738.95,2551.83) 2793.3,2551.83 2811.17,2533.96 2832.97,2533.96 2837.97,2528.96 C71.1@2837.97,2521.46 2840.64,2518.79 U11.4@2920.44,2518.79 ; R31.2@3023.44,1390.22 3024.2,1390.98 3061.25,1390.98 v1(3062.01,1391.75) ; R98.2@3050.82,2680.38 3075.91,2680.38 3087.63,2668.67 v1(3091.31,2668.67) ; TP18.1@3057.06,3064.09 3057.06,2916.36 3089.11,2884.32 R117.2@3089.11,2876.82 ; R118.2@3131.14,1040.65 3136.14,1035.65 3136.14,1020.65 3146.84,1009.94 3214.66,1009.94 3209.66,1004.94 3183.02,1004.94 3162.82,984.74 3154.94,984.74 3148.13,977.93 U15.5@3148.13,970.05
  other v1: 3116.61,1074.49 3153.45,1074.49 3190.29,1074.49 3227.13,1074.49
5V: C67.1 C68.1 C69.1 C70.1 C79.1 C87.1 C88.1 C89.1 C90.1 L1.2 L2.2 R73.1 R75.2 R76.1 R77.2 R78.2 R109.2 R110.2 R111.2 TP17.1 U1.5 U2.5 U3.5 U4.5 U5.4 U6.4 U8.4 U9.4 U14.1 | length 1670.6
  Top Layer w10: v1(2595.91,872.03) v1@2597.32,873.44
  Bottom Layer w10: U4.5@1612,982.5 1611.49,983.01 1611.49,1037.54 1610.98,1038.05 v1(1648.89,1038.05) ; U3.5@1612,1678.03 1611.49,1678.54 1611.49,1733.07 C89.1@1610.98,1733.62 v1(1648.89,1733.58) ; U2.5@1612,2373.58 1611.49,2374.07 1611.49,2428.6 C88.1@1610.98,2429.13 v1(1648.89,2429.11) ; U1.5@1612,3069.09 1611.49,3069.6 1611.49,3124.13 C87.1@1610.98,3124.64 v1(1648.89,3124.64) ; v1@1858.7,2319.92 1928.97,2319.92 1929.12,2320.07 C68.1@1953.66,2295.53 ; v1(1862.44,3014.96) 1922.24,3014.96 1941.16,2996.04 1948.66,2996.04 1953.74,2990.97 C67.1@1953.66,2983.54 U5.4@2024.45,2983.46 ; v1(1866.2,1627.24) 1926.44,1627.24 C69.1@1953.66,1600.02 ; v1(1867.11,931.73) 1869.3,933.93 1924.24,933.93 C70.1@1953.66,904.51 ; C70.1@1953.66,897.01 1953.74,896.93 U9.4@2024.45,896.93 ; C69.1@1953.66,1592.52 1953.74,1592.44 U8.4@2024.45,1592.44 ; C68.1@1953.66,2288.03 C68.1@1953.66,2288.03 U6.4@2024.45,2287.95 ; v1(2047.89,1039.84) 2048.31,1040.26 R78.2@2048.31,1073.17 ; R77.2@2050.44,1775.92 2052.94,1773.42 2052.94,1763.92 2053.47,1763.4 v1(2053.47,1737.98) ; R75.2@2050.47,3181.78 2052.97,3179.28 2052.97,3165.8 2055.15,3163.62 v1(2055.15,3136.81) v1@2056.13,3136.81 ; v1(2051.17,2441.29) 2051.17,2477.24 R76.1@2053.67,2479.74 ; TP17.1@2696.87,3064.09 2696.87,2904.5 2717.06,2884.32 R111.2@2717.06,2876.82 ; v1(2731.94,2322.7) 2783.49,2322.7 R73.1@2783.71,2322.92 ; L1.2@2844.7,1393.86 2845.81,1392.75 2845.81,1346.34 v1(2846.6,1345.55) ; v1(2875.01,1818.75) 2877.62,1821.35 2877.62,1837.06 2901.57,1861.01 L2.2@2901.57,1868.51 ; v1(2895.62,971.61) 2930.1,937.13 2930.1,912.78 R109.2@2935.1,907.78
  other v1: 2595.91,837.03 2635.31,837.03 2669.33,837.48 2633.56,872.03 1866.38,2319.92
5V25: C80.2 C81.1 J5.48 J5.84 J5.98 J5.112 L3.2 R106.2 R107.2 R108.1 R116.1 TP16.1 | length 1925.7
  Top Layer w10: J5.112@3576.28,968.59 3577.93,970.24 3794.94,970.24 v1(3796.59,971.89) ; J5.98@3576.28,1189.06 v1(3802.47,1189.06) ; J5.84@3576.28,1409.54 3576.66,1409.91 3764.71,1409.91 3778.72,1423.91 v1(3782.4,1423.91) ; J5.48@3576.28,2102.45 v1(3756.34,2102.45)
  Bottom Layer w10: R116.1@3141.75,766.07 3141.75,758.57 3163.43,736.89 R107.2@3163.43,520.53 ; R108.1@3221.73,2870.02 R108.1@3221.73,2877.52 3221.73,2885.02 3243.15,2906.44 TP16.1@3243.15,3064.09 3253.15,3054.09 3776.49,3054.09 3834.65,2995.94 v1(3834.65,2987.41)
  other v1: 2967.08,772.36 3002.99,771.71 3038.45,772.02 3074.33,772.02
ADC_BUSY: J5.85 R46.2 | length 444.2
  Top Layer w10: v1(3184.52,1515.38) 3184.52,1435.02 3243,1376.54 3323.59,1376.54 3325.09,1378.04 J5.85@3442.42,1378.04
  Bottom Layer w10: R46.2@3103.63,1514.79 3183.94,1514.79 v1(3184.52,1515.38)
ADC_CONVST: R85.1 R86.2 U7.19 | length 471
  Top Layer w10: v1(3114.13,1700.3) 3147.99,1734.16 3147.99,1774.24 3289.82,1916.06 R86.2@3294.32,1916.06 3294.39,1916.14 3294.39,1976.39 R85.1@3294.47,1976.46
  Bottom Layer w10: U7.19@3013.66,1659.24 3013.74,1659.32 3033.44,1659.32 3074.41,1700.3 v1(3114.13,1700.3)
ADC_M0: J5.51 R52.2 U7.17 | length 635.8
  Top Layer w10: v1(3329.17,2036.26) 3330.77,2037.86 3440.82,2037.86 J5.51@3442.42,2039.46
  Bottom Layer w10: U7.17@3013.66,1698.61 3020.4,1698.61 3062.83,1741.05 3062.83,1770.99 R52.2@3067.01,1775.17 ; R52.2@3070,1772.19 3094.5,1796.69 3094.5,1881.74 3251.73,2038.97 v1@3328.25,2038.97
ADC_M1: J5.49 R51.2 U7.16 | length 673.7
  Top Layer w10: v1(3329.29,2069.39) 3330.07,2070.17 3441.64,2070.17 J5.49@3442.42,2070.95
  Bottom Layer w10: U7.16@2988.07,1724.2 2988.07,1730.94 3007.64,1750.51 3007.64,1762.14 3009.62,1764.11 3009.62,1813.03 3010.82,1814.22 R51.2@3010.82,1818.72 3010.82,1876.85 3204.92,2070.95 v1@3328.25,2070.95
ADC_NCS: R42.1 R96.1 R97.1 U7.21 | length 607.8
  Top Layer w10: R42.1@3256.02,1441.22 3256.12,1441.13 3294.38,1441.13 R97.1@3294.47,1441.03 3294.47,1445.53 3291.97,1448.03 3273.37,1448.03 3219.89,1501.51 3219.89,1529.52 3249.81,1559.43 3291.97,1559.43 3294.47,1561.93 R96.1@3294.47,1566.43 3291.97,1568.93 3291.97,1573.43 3277.78,1587.63 v1(3256.02,1587.63)
  Bottom Layer w10: 3030.18,1619.95 3013.74,1619.95 U7.21@3013.66,1619.87 3044.54,1619.87 3073.94,1649.28 3194.37,1649.28 v1(3256.02,1587.63)
ADC_RD: R86.1 R87.1 U7.20 | length 446.5
  Top Layer w10: v1(3149.81,1684.3) 3176.2,1710.69 3176.2,1769.19 3226,1818.98 R87.1@3294.47,1818.98 3294.39,1819.06 3294.39,1875.99 R86.1@3294.32,1876.06
  Bottom Layer w10: U7.20@3013.66,1639.56 3038.95,1639.56 3066.54,1667.15 3129.04,1667.15 3146.19,1684.3 v1(3149.81,1684.3)
ADC_SCLK: J5.71 J5.79 R43.1 R92.1 U7.22 | length 1185
  Top Layer w10: v1(3129.74,1622.9) 3262.83,1755.99 3268.84,1755.99 ; 3141.7,1628.85 3268.84,1755.99 ; R92.1@3290.63,1755.99 3268.84,1755.99 ; v1(3305.87,1605.02) 3337.15,1605.02 3343.66,1598.51 J5.71@3442.42,1598.51 ; v1(3325,1492.6) 3345.07,1472.53 J5.79@3442.42,1472.53
  Bottom Layer w10: U7.22@3013.66,1600.19 3050.97,1600.19 ; v1(3129.74,1622.9) 3073.68,1622.9 3050.97,1600.19 ; v1(3305.87,1605.02) 3305.87,1574.6 3274.43,1543.16 ; v1(3325,1492.6) 3274.43,1543.16 ; 3050.97,1600.19 3065.9,1585.26 R43.1@3065.9,1580.76 3065.9,1576.26 3099,1543.16 3274.43,1543.16
ADC_SDI: R95.1 U7.18 | length 339.6
  Top Layer w10: v1(3251.5,1632.79) 3253.95,1632.79 3265.37,1644.2 R95.1@3287.87,1644.2
  Bottom Layer w10: U7.18@3013.66,1678.93 3013.74,1679.01 3027.84,1679.01 3077.13,1728.29 3157.09,1728.29 3251.5,1633.88 v1(3251.5,1632.79)
ADC_SDOA: J5.67 R47.2 | length 532
  Top Layer w10: v1(3140.17,1430.36) 3137.95,1432.58 3137.95,1554.15 3268.1,1684.3 3321.77,1684.3 3335.79,1670.28 3357.95,1670.28 3359.87,1670.28 3368.65,1661.5 J5.67@3442.42,1661.5
  Bottom Layer w10: R47.2@3102.01,1427.25 3103.57,1428.81 3138.61,1428.81 v1(3140.17,1430.36)
ADC_SDOB: J5.75 R48.2 | length 367.8
  Top Layer w10: v1(3262.83,1512.29) 3262.83,1513.76 3284.59,1535.52 J5.75@3442.42,1535.52
  Bottom Layer w10: R48.2@3102.45,1470.47 3221.01,1470.47 v1(3262.83,1512.29)
CH1+: J1.1 T1.1
CH1-: J1.2 T1.2
CH1_Filt_In: R2.2 R23.1 R30.2 TP2.1 U1.1 | length 791.2
  Bottom Layer w10: R2.2@1445.28,3023.94 1450.28,3018.94 1472.74,3018.94 1478.23,3013.45 1603.67,3013.45 1612,3005.12 U1.1@1612,2960.83 1770.61,2960.83 1794.8,2936.63 1794.8,2929.13 1794.8,2795.06 TP2.1@1843.07,2746.79 1845.61,2744.25 1997.2,2744.25 2002.2,2739.25 R30.2@2002.2,2731.75
CH1_Filt_Out: R27.1 R29.1 TP1.1 U5.15 U5.16 | length 467.2
  Bottom Layer w10: U5.16@2252.8,2906.69 2254.53,2908.43 2291.22,2908.43 2297.14,2914.35 ; U5.15@2252.8,2932.28 2289.02,2932.28 2297.14,2924.16 2297.14,2914.35 ; R27.1@2311.38,2746.79 R27.1@2311.38,2754.29 2311.38,2761.79 2378.31,2828.72 ; TP1.1@2421.55,2760.83 2378.31,2804.07 2378.31,2828.72 ; 2297.14,2914.35 2297.14,2902.99 2378.15,2902.99 R29.1@2378.31,2902.83 2378.31,2828.72
CH1_Out: R27.2 R30.1 R39.1 R79.2 | length 2352.2
  Bottom Layer w10: R30.1@2062.2,2731.75 2062.2,2739.25 2090.5,2767.55 2206.9,2767.55 ; 2206.93,2767.58 2220.23,2754.29 R27.2@2251.38,2754.29 R27.2@2251.38,2752.87 ; R27.2@2246.38,2747.87 R27.2@2251.38,2752.87 ; R39.1@2692.13,1750.61 2692.13,2313.54 2338.03,2667.63 ; R79.2@3230.23,2707.25 3222.73,2707.25 3184.14,2745.83 2785.69,2745.83 2707.49,2667.63 2338.03,2667.63 ; R27.2@2251.38,2752.87 2251.38,2746.79 2256.38,2741.79 2263.88,2741.79 2338.03,2667.63
CH2+: J2.1 T2.1
CH2-: J2.2 T2.2
CH2_Filt_In: R7.2 R34.1 R44.2 TP4.1 U2.1 | length 757
  Bottom Layer w10: R7.2@1450.81,2332.04 1589.55,2332.04 1612,2309.58 U2.1@1612,2265.31 1762.74,2265.31 1786.93,2241.12 R34.1@1786.93,2233.62 1786.93,2139.26 TP4.1@1855.68,2070.52 1874.37,2070.52 1900.03,2044.86 R44.2@2003.24,2044.86
CH2_Filt_Out: R38.1 R41.1 TP3.1 U6.15 U6.16 | length 463.2
  Bottom Layer w10: U6.16@2252.8,2211.18 2254.53,2212.91 2291.22,2212.91 2297.14,2218.84 ; U6.15@2252.8,2236.77 2289.02,2236.77 2297.14,2228.65 2297.14,2218.84 ; R38.1@2311.37,2051.28 2311.37,2066.28 2378.31,2133.21 ; TP3.1@2431.36,2070.52 2378.31,2123.57 2378.31,2133.21 ; 2297.14,2218.84 2297.14,2207.48 2373.31,2207.48 2378.31,2202.48 R41.1@2378.31,2201.99 2378.31,2133.21
CH2_Out: R38.2 R44.1 R45.1 R80.2 | length 1644.5
  Top Layer w10: v1(2612.95,2001.57) 2635.07,2023.69 2635.07,2492.53 v1(2738.09,2595.56)
  Bottom Layer w10: R44.1@2063.24,2052.36 2087.76,2052.36 2107.44,2072.04 2206.9,2072.04 ; 2206.93,2072.07 2220.22,2058.78 R38.2@2251.38,2058.78 R38.2@2251.37,2057.36 ; R38.2@2246.37,2052.36 R38.2@2251.37,2057.36 ; R38.2@2251.37,2051.28 R38.2@2251.37,2057.36 ; R38.2@2251.38,2058.78 2251.38,2051.28 2256.38,2046.28 2263.87,2046.28 2278.17,2046.28 2322.87,2001.57 v1(2612.95,2001.57) 2656.32,1958.2 2656.32,1723.35 2669.05,1710.63 R45.1@2692.13,1710.63 ; v1(2738.09,2595.56) R80.2@2793.47,2595.56
CH3+: J3.1 T3.1
CH3-: J3.2 T3.2
CH3_Filt_In: R12.2 R53.1 R61.2 TP6.1 U3.1 | length 885.2
  Bottom Layer w10: R12.2@1440.7,1625.41 1443.72,1622.39 1603.66,1622.39 1612,1614.05 U3.1@1612,1569.8 ; U3.1@1612,1569.8 1667.44,1569.8 ; R53.1@1786.93,1538.11 1786.93,1545.61 1762.74,1569.8 1667.44,1569.8 ; R61.2@1978.21,1864.62 1978.21,1857.12 1973.21,1852.12 1944.52,1852.12 1914.18,1821.78 1864.65,1821.78 TP6.1@1855.68,1812.81 1850.35,1812.81 1667.44,1629.89 1667.44,1569.8
CH3_Filt_Out: R57.1 R59.1 TP5.1 U8.10 U8.11 | length 535.9
  Bottom Layer w10: U8.11@2252.8,1643.62 2256.65,1647.48 2291.29,1647.48 2297.14,1653.34 2297.14,1662.54 2292.2,1667.48 ; U8.10@2252.8,1669.21 2254.53,1667.48 2292.2,1667.48 ; R57.1@2298.84,1826.22 2298.84,1818.72 R57.1@2303.84,1813.72 ; TP5.1@2431.36,1791.97 TP5.1@2431.36,1812.81 2430.45,1813.72 R57.1@2303.84,1813.72 ; 2292.2,1667.48 2302.42,1677.7 2302.42,1693.7 2312.64,1703.92 2387.26,1703.92 R59.1@2387.73,1703.45 2387.73,1734.49 2344.47,1777.75 2339.81,1777.75 R57.1@2303.84,1813.72
CH3_Out: R57.2 R60.1 R61.1 R83.2 | length 1762.3
  Top Layer w10: v1(2655.14,1632.9) 2655.14,2392.53 v1@2729.02,2466.41
  Bottom Layer w10: R61.1@2037.29,1860.68 2204.38,1860.68 2226.34,1838.72 2233.84,1838.72 R57.2@2238.84,1833.72 ; R57.2@2238.84,1826.22 R57.2@2238.84,1833.72 ; R60.1@2692.08,1630.68 2690.98,1631.79 2656.24,1631.79 2638.45,1649.59 2638.45,1749.12 2514.85,1872.72 2285.34,1872.72 2251.34,1838.72 2243.84,1838.72 R57.2@2238.84,1833.72 ; v1(2729.49,2466.89) 2777.26,2466.89 R83.2@2778.87,2468.49
CH4+: J4.1 T4.1
CH4-: J4.2 T4.2
CH4_Filt_In: R17.2 R65.1 R72.2 TP7.1 U4.1 | length 870.2
  Bottom Layer w10: R17.2@1446.6,939.99 1454.1,939.99 1467.23,926.86 1603.67,926.86 1612,918.52 U4.1@1612,874.29 1667.43,874.29 ; R65.1@1779.05,842.6 1779.05,850.1 1754.86,874.29 1667.43,874.29 ; R72.2@1972.84,1169.11 1972.84,1161.61 1928.52,1117.3 1850.35,1117.3 1667.43,934.38 1667.43,874.29
CH4_Filt_Out: R69.2 R71.1 TP8.1 U9.10 U9.11 | length 483.5
  Bottom Layer w10: U9.11@2252.8,948.11 2256.65,951.97 2291.29,951.97 2297.14,957.83 2297.14,967.03 2292.2,971.97 ; U9.10@2252.8,973.7 2254.53,971.97 2292.2,971.97 ; R69.2@2298.84,1127.15 2298.84,1123.21 2303.84,1118.21 2311.34,1118.21 2312.25,1117.3 TP8.1@2417.73,1117.3 ; TP8.1@2432.58,1132.15 TP8.1@2417.73,1117.3 ; 2292.2,971.97 2302.42,982.19 2302.42,998.19 2315.34,1011.1 R71.1@2375.46,1011.1 2375.46,1075.02 TP8.1@2417.73,1117.3
CH4_Out: R62.1 R69.1 R72.1 R84.2 | length 2264.5
  Top Layer w10: v1(2687.87,1511.77) 2687.87,2237.14 2792.74,2342.01 v1(3175.36,2342.01)
  Bottom Layer w10: R72.1@2032.84,1169.11 2058.58,1143.37 2226.18,1143.37 2226.34,1143.21 2233.84,1143.21 R69.1@2238.84,1138.21 ; R69.1@2238.84,1130.71 R69.1@2238.84,1138.21 ; R62.1@2692.1,1585.02 2689.99,1582.91 2689.99,1513.88 v1(2687.87,1511.77) 2687.87,1439.84 2488.19,1240.16 2348.3,1240.16 2251.34,1143.21 2243.84,1143.21 R69.1@2238.84,1138.21 ; v1(3175.36,2342.01) 3179.05,2342.01 3193.72,2356.68 R84.2@3230.23,2356.68
CT1_OUT+: R4.1 R5.2 T1.3 | length 296.2
  Bottom Layer w10: R5.2@1243.62,2964.45 T1.3@1243.62,3132.5 ; 1296.26,2959.45 R5.2@1248.99,2959.45 1288.05,2959.45 1327.11,2959.45 R4.1@1329.08,2957.48
CT1_OUT-: C1.2 C2.1 D1.1 D1.2 R1.1 R5.1 R120.2 T1.4 | length 390.3
  Signal Layer 2 w20: v1@1359.08,2795.13 v1(1359.08,3133.06)
  Bottom Layer w10: R5.1@1243.62,2894.45 1248.62,2899.45 R5.1@1248.99,2899.45 ; v1(1359.08,3133.06) 1392.97,3133.06 1397.97,3128.06 R1.1@1397.97,3124.09
  other v1: 1359.55,2794.66
CT2_OUT+: R9.1 R10.2 T2.3 | length 248.1
  Bottom Layer w10: R10.2@1243.62,2268.91 T2.3@1243.62,2436.97 ; R10.2@1248.99,2263.94 1287.61,2263.94 1326.24,2263.94 R9.1@1328.23,2261.94
CT2_OUT-: C3.2 C4.1 D2.1 D2.2 R6.1 R10.1 R121.2 T2.4 | length 401.1
  Signal Layer 2 w20: v1(1351.17,2441.13) 1351.17,2440.15 1358.23,2433.09 1358.23,2105.27 1351.87,2098.91 v1(1351.87,2097.93)
  Bottom Layer w10: R10.1@1243.62,2198.91 1248.62,2203.91 R10.1@1248.99,2203.94 ; v1(1351.17,2441.13) 1385.05,2441.13 1390.05,2436.13 R6.1@1390.05,2432.17
CT3_OUT+: R14.1 R15.2 T3.3 | length 295.4
  Bottom Layer w10: R15.2@1243.62,1573.38 T3.3@1243.62,1741.44 ; 1296.26,1568.38 R15.2@1248.99,1568.42 1287.6,1568.42 1326.22,1568.42 R14.1@1328.23,1566.41
CT3_OUT-: C5.2 C6.1 D3.1 D3.2 R11.1 R15.1 R122.2 T3.4 | length 377.5
  Signal Layer 2 w20: T3.4@1243.62,1341.44 T3.4@1243.62,1348.26 ; v1(1354.01,1416.87) 1354.01,1737.14 1358.36,1741.49 v1(1358.36,1742.47)
  Bottom Layer w10: R15.1@1243.62,1503.38 1248.62,1508.38 R15.1@1248.99,1508.42 ; v1(1358.36,1742.47) 1393.41,1742.47 R11.1@1393.96,1741.92
CT4_OUT+: R19.1 R20.2 T4.3 | length 248.8
  Bottom Layer w10: R20.2@1243.62,877.85 T4.3@1243.62,1045.91 ; R20.2@1248.99,872.91 1295.17,872.91 1295.22,872.87 1324.64,872.87 R19.1@1328.23,876.45
CT4_OUT-: C7.2 C8.1 D4.1 D4.2 R16.1 R20.1 R123.2 T4.4 | length 399.4
  Signal Layer 2 w20: v1(1347.4,703.95) v1(1347.4,1051.04)
  Bottom Layer w10: R20.1@1243.62,807.85 1248.62,812.85 R20.1@1248.99,812.91 ; v1(1347.4,1051.04) 1381.28,1051.04 1386.28,1046.04 R16.1@1386.28,1042.07
Ext_INT: J5.86 J6.4 R99.2 | length 2831.2
  Top Layer w10: J6.4@3042.75,3574.8 3156.23,3574.8 3857.01,2874.02 3857.01,1463.61 3771.71,1378.32 3767.21,1378.32 3767.07,1378.18 3586.11,1378.18 3585.98,1378.32 3576.56,1378.32 J5.86@3576.28,1378.04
